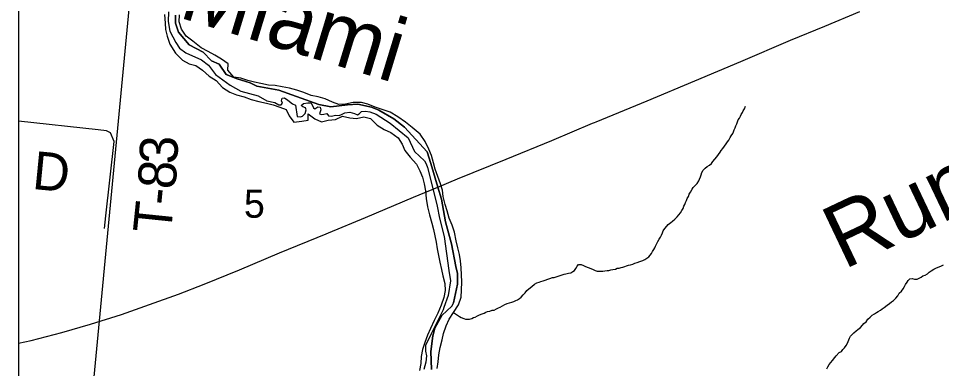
# Model space of a CAD drawing. Extents: x 0.4 to 34.4, y -2.1 to 19.9.
# Drawn here: x 3 to 4.379, y 13.669 to 14.193 of the extents above; entities that cross this region are included whole.
import ezdxf

# ---------------------------------------------------------------- set-up
doc = ezdxf.new("R2010")
doc.units = 0
for name, color, linetype in [('GM_X_County', 7, 'Continuous'), ('GM_X_Interstate_Route', 7, 'Continuous'), ('GM_X_Major_River', 7, 'Continuous'), ('GM_X_Major_River_Text', 7, 'Continuous'), ('GM_X_Minor_River', 7, 'Continuous'), ('GM_X_Minor_River_Text', 7, 'Continuous'), ('GM_X_Section', 7, 'Continuous'), ('GM_X_Section_Text', 7, 'Continuous'), ('GM_X_Township', 7, 'Continuous'), ('GM_X_Township_Road', 7, 'Continuous'), ('GM_X_Township_Road_Text', 7, 'Continuous'), ('SH_Data', 7, 'Continuous')]:
    doc.layers.add(name, color=color, linetype=linetype)

msp = doc.modelspace()

# ---------------------------------------------------------------- linework, layer by layer
at = {"layer": 'GM_X_County'}
msp.add_lwpolyline([(9.8001, 15.3423), (9.8001, 18.8357), (3.0001, 18.8357), (3.0001, 12.0357), (9.5074, 12.0357)], dxfattribs=at)
at = {"layer": 'GM_X_Interstate_Route'}
for points in [[(3.8604, 14.0372), (3.8629, 14.0382), (3.9389, 14.0693), (4.0101, 14.0992), (4.0789, 14.1281), (4.153, 14.16), (4.2044, 14.181), (4.2569, 14.2032)], [(3.4632, 13.872), (3.5184, 13.895), (3.5903, 13.9254), (3.6265, 13.9405), (3.656, 13.9528), (3.7287, 13.9823), (3.7967, 14.0104), (3.8573, 14.0359), (3.8604, 14.0372)], [(3.0001, 13.7072), (3.0189, 13.7114), (3.0649, 13.7234), (3.1078, 13.7355), (3.1538, 13.7502), (3.1959, 13.7649), (3.2393, 13.7804), (3.2777, 13.7955), (3.3301, 13.817), (3.3902, 13.8421), (3.4598, 13.8706), (3.4632, 13.872)]]:
    msp.add_lwpolyline(points, dxfattribs=at)
at = {"layer": 'GM_X_Major_River'}
for points in [[(3.2182, 14.1987), (3.2191, 14.1854), (3.2197, 14.1759), (3.2222, 14.166), (3.2262, 14.1542), (3.2348, 14.1408), (3.2452, 14.1304), (3.255, 14.1249), (3.2648, 14.1225), (3.275, 14.1155), (3.2851, 14.1066), (3.2952, 14.1), (3.3049, 14.0893), (3.3158, 14.0826), (3.326, 14.0787), (3.337, 14.0755), (3.3479, 14.0715), (3.3589, 14.0683), (3.3706, 14.0658), (3.3804, 14.0634), (3.3903, 14.0599), (3.4001, 14.0567), (3.4045, 14.0471), (3.4115, 14.0375), (3.4233, 14.0392), (3.4328, 14.0406), (3.433, 14.0501)], [(3.6269, 13.6796), (3.6278, 13.6898), (3.6299, 13.7008), (3.6327, 13.7121), (3.6351, 13.7219), (3.6387, 13.7332), (3.6434, 13.7434), (3.65, 13.7532), (3.6571, 13.7648), (3.6614, 13.7761), (3.662, 13.7867), (3.6625, 13.7989), (3.6616, 13.8095), (3.6613, 13.8201), (3.6604, 13.8304), (3.659, 13.8399), (3.6565, 13.8498), (3.6536, 13.8604), (3.6512, 13.873), (3.6479, 13.8837), (3.6435, 13.894), (3.6403, 13.905), (3.6374, 13.9145), (3.6345, 13.9267), (3.6332, 13.9362), (3.6306, 13.9457), (3.6263, 13.9564), (3.6226, 13.9675), (3.6201, 13.977), (3.6169, 13.9877), (3.6132, 13.9972), (3.6077, 14.0087), (3.5999, 14.0198), (3.5883, 14.0298), (3.5782, 14.0376), (3.5669, 14.0457), (3.5553, 14.0527), (3.5447, 14.0563), (3.533, 14.0603), (3.522, 14.0646), (3.5122, 14.0671), (3.5001, 14.0669), (3.4886, 14.0644), (3.4788, 14.0642), (3.4689, 14.0674), (3.458, 14.0725), (3.4478, 14.0753), (3.4372, 14.0777), (3.4263, 14.0821), (3.4157, 14.0853), (3.4047, 14.0885), (3.3938, 14.0905), (3.3835, 14.0922), (3.3733, 14.0927), (3.3623, 14.0952), (3.3525, 14.0976), (3.3427, 14.1), (3.3321, 14.1032), (3.3219, 14.1049), (3.3129, 14.1153), (3.3131, 14.1248), (3.3033, 14.1318), (3.2935, 14.1376), (3.2834, 14.1431), (3.2728, 14.1485), (3.2605, 14.1586), (3.2507, 14.1663), (3.2437, 14.1767), (3.24, 14.1874), (3.2406, 14.198)], [(3.433, 14.0501), (3.4427, 14.0424), (3.4525, 14.038), (3.4628, 14.0405), (3.4735, 14.0415), (3.4842, 14.0466), (3.4948, 14.0442), (3.505, 14.0429), (3.5157, 14.0458), (3.5259, 14.043), (3.536, 14.0333), (3.5461, 14.0267), (3.5563, 14.022), (3.5672, 14.0142), (3.5731, 14.0047), (3.5771, 13.9951), (3.585, 13.9851), (3.5947, 13.9751), (3.5998, 13.9648), (3.6035, 13.9553), (3.606, 13.9454), (3.6081, 13.9351), (3.6091, 13.9237), (3.6108, 13.9112), (3.614, 13.899), (3.6176, 13.8868), (3.6201, 13.8773), (3.6222, 13.8678), (3.624, 13.8582), (3.6253, 13.8484), (3.6275, 13.8381), (3.6292, 13.8282), (3.6317, 13.8175), (3.6338, 13.808), (3.6367, 13.7966), (3.6373, 13.786), (3.6356, 13.7754), (3.6316, 13.7641), (3.6265, 13.752), (3.621, 13.7411), (3.6155, 13.7291), (3.6112, 13.7193), (3.6072, 13.7083), (3.6036, 13.6978), (3.6016, 13.6872), (3.601, 13.6769), (3.599, 13.6667)], [(3.6252, 13.6694), (3.6269, 13.6796)]]:
    msp.add_lwpolyline(points, dxfattribs=at)
at = {"layer": 'GM_X_Minor_River'}
for points in [[(3.9572, 13.8629), (3.9588, 13.8659), (3.9604, 13.8689), (3.962, 13.8723), (3.9632, 13.875), (3.9652, 13.8787), (3.9683, 13.8821), (3.9703, 13.8847), (3.9742, 13.8877), (3.9769, 13.8899), (3.9804, 13.8929), (3.9839, 13.8963), (3.9866, 13.8993), (3.989, 13.9023), (3.991, 13.9057), (3.9926, 13.9087), (3.9938, 13.9121), (3.9954, 13.9147), (3.9962, 13.9177), (3.9978, 13.9208), (3.999, 13.9234), (4.0006, 13.9264), (4.0018, 13.9298), (4.0038, 13.9332), (4.0065, 13.9373), (4.0077, 13.94), (4.0113, 13.9433), (4.0136, 13.946), (4.016, 13.9497), (4.0172, 13.9524), (4.0188, 13.9561), (4.0196, 13.9588), (4.0208, 13.9626), (4.0228, 13.966), (4.0259, 13.9689), (4.0287, 13.9712), (4.0321, 13.9734), (4.0349, 13.976), (4.0372, 13.9786), (4.0403, 13.9824), (4.0431, 13.9857), (4.0458, 13.9895), (4.0482, 13.9929), (4.0498, 13.9955), (4.0521, 13.9985), (4.0545, 14.0019), (4.0569, 14.0053), (4.0592, 14.0083), (4.0612, 14.0109), (4.0632, 14.0147), (4.0644, 14.0173), (4.0668, 14.0207), (4.068, 14.0233), (4.0692, 14.026), (4.0704, 14.029), (4.0716, 14.032), (4.0728, 14.0351), (4.074, 14.0381), (4.0752, 14.0411), (4.0768, 14.0437), (4.0784, 14.0464), (4.0796, 14.049), (4.0812, 14.052), (4.0824, 14.0547), (4.0844, 14.0577), (4.086, 14.0614)], [(3.65, 13.7532), (3.6587, 13.7474), (3.6614, 13.7458), (3.6652, 13.7442), (3.6678, 13.7434), (3.6705, 13.743), (3.6735, 13.7433), (3.677, 13.7444), (3.6797, 13.7455), (3.6824, 13.7462), (3.6858, 13.748), (3.6885, 13.7495), (3.6924, 13.7513), (3.6955, 13.7524), (3.6982, 13.7535), (3.7008, 13.7546), (3.7043, 13.7553), (3.7077, 13.7564), (3.7104, 13.7567), (3.7139, 13.7585), (3.717, 13.76), (3.7197, 13.7611), (3.7231, 13.7629), (3.7266, 13.7652), (3.7301, 13.7666), (3.7336, 13.7677), (3.737, 13.7688), (3.7397, 13.7695), (3.7428, 13.7709), (3.7455, 13.772), (3.7482, 13.7739), (3.7509, 13.7761), (3.754, 13.7795), (3.7568, 13.7825), (3.7595, 13.7859), (3.7622, 13.7885), (3.7669, 13.7922), (3.7708, 13.7955), (3.7743, 13.7974), (3.7777, 13.7985), (3.7804, 13.7996), (3.7839, 13.8006), (3.7865, 13.8013), (3.7908, 13.8028), (3.7938, 13.8039), (3.7977, 13.8053), (3.8004, 13.8057), (3.803, 13.8064), (3.8061, 13.8075), (3.8092, 13.8085), (3.8119, 13.8093), (3.815, 13.8103), (3.8176, 13.8107), (3.8215, 13.8117), (3.8249, 13.8124), (3.828, 13.8143), (3.8307, 13.8161), (3.8327, 13.8188), (3.8343, 13.8222), (3.8366, 13.8248), (3.8405, 13.8251), (3.8442, 13.8235), (3.8472, 13.8219), (3.851, 13.8203), (3.8548, 13.8187), (3.8582, 13.8175), (3.8616, 13.816), (3.8642, 13.8151), (3.8696, 13.8147), (3.873, 13.815), (3.8757, 13.8153), (3.8791, 13.816), (3.8818, 13.816), (3.8849, 13.8167), (3.8876, 13.8174), (3.8918, 13.8181), (3.8945, 13.8192), (3.8971, 13.8195), (3.9002, 13.8202), (3.9029, 13.8209), (3.9056, 13.822), (3.9083, 13.8227), (3.911, 13.8238), (3.9144, 13.8245), (3.9175, 13.8256), (3.9206, 13.8267), (3.924, 13.8277), (3.9279, 13.8292), (3.9325, 13.831), (3.9356, 13.8325), (3.9386, 13.8343), (3.9414, 13.8362), (3.9433, 13.8388), (3.9453, 13.8414), (3.9469, 13.8441), (3.9488, 13.8471), (3.9504, 13.8497), (3.9516, 13.8524), (3.9536, 13.8561), (3.9552, 13.8595), (3.9572, 13.8629)], [(4.2401, 13.7124), (4.241, 13.715), (4.2429, 13.7177), (4.2476, 13.7229), (4.2511, 13.7255), (4.2538, 13.7277), (4.2577, 13.7307), (4.2605, 13.7341), (4.2628, 13.7367), (4.2659, 13.7393), (4.2687, 13.7431), (4.2722, 13.7464), (4.2753, 13.7494), (4.2784, 13.7513), (4.2815, 13.7531), (4.2842, 13.7546), (4.2873, 13.7564), (4.29, 13.7587), (4.2931, 13.7605), (4.2974, 13.7639), (4.3008, 13.7665), (4.304, 13.7691), (4.3071, 13.7713), (4.3106, 13.7746), (4.3133, 13.778), (4.3153, 13.7818), (4.3188, 13.7848), (4.3212, 13.7885), (4.3235, 13.7919), (4.3251, 13.7949), (4.3275, 13.7983), (4.3291, 13.8009), (4.3314, 13.8036), (4.3349, 13.8039), (4.3383, 13.8031), (4.3421, 13.803), (4.3452, 13.8045), (4.3482, 13.8059), (4.351, 13.8078), (4.3544, 13.8092), (4.3575, 13.8111), (4.3602, 13.8133), (4.3633, 13.8152), (4.3672, 13.8177), (4.3703, 13.8192), (4.3737, 13.8207), (4.3776, 13.8225), (4.3814, 13.8243)], [(4.2075, 13.6689), (4.2091, 13.6719), (4.2111, 13.6753), (4.2135, 13.6786), (4.2158, 13.6816), (4.2193, 13.6858), (4.2213, 13.6884), (4.226, 13.6933), (4.2291, 13.6951), (4.2314, 13.6977), (4.2338, 13.7003), (4.2365, 13.7037), (4.2385, 13.7071), (4.2393, 13.7097), (4.2401, 13.7124)]]:
    msp.add_lwpolyline(points, dxfattribs=at)
at = {"layer": 'GM_X_Section'}
msp.add_line((3.0001, 14.5041), (3.0001, 13.5939), dxfattribs=at)
for points in [[(3.0001, 13.5939), (3.106, 13.5839), (3.192, 14.4845), (3.0001, 14.5041)], [(3.106, 13.5839), (3.192, 14.4845)], [(3.2242, 14.2025), (3.2236, 14.1882), (3.2264, 14.1737), (3.2352, 14.1569), (3.2407, 14.1481), (3.2501, 14.1415), (3.2737, 14.1309), (3.2838, 14.1227), (3.2942, 14.1089), (3.3163, 14.093), (3.332, 14.084), (3.358, 14.0771), (3.3711, 14.0697), (3.3832, 14.0669), (3.3888, 14.0637), (3.3926, 14.0637), (3.3946, 14.0659), (3.3931, 14.0697), (3.3939, 14.0735), (3.3973, 14.0738), (3.4022, 14.0707), (3.4093, 14.0649), (3.4138, 14.0629), (3.4166, 14.0462), (3.4215, 14.0454), (3.4245, 14.0465), (3.4284, 14.0506), (3.43, 14.0562), (3.4289, 14.0589), (3.4248, 14.0605), (3.4221, 14.0624), (3.4259, 14.0655), (3.4321, 14.0664), (3.4374, 14.0663), (3.4406, 14.059), (3.4429, 14.0575), (3.4471, 14.0605), (3.4505, 14.06), (3.4516, 14.0562), (3.4499, 14.0502), (3.4522, 14.049), (3.456, 14.0497), (3.4609, 14.0507), (3.4632, 14.0473), (3.4677, 14.0468), (3.4734, 14.0479), (3.4791, 14.0474), (3.4825, 14.0489), (3.4875, 14.0518), (3.4951, 14.0528), (3.5018, 14.0508), (3.5067, 14.0488), (3.509, 14.0499), (3.5125, 14.0536), (3.5182, 14.0543), (3.525, 14.053), (3.5344, 14.0495), (3.555, 14.0362), (3.5819, 14.0142), (3.5914, 13.994), (3.6065, 13.9797), (3.609, 13.9753), (3.611, 13.9701), (3.617, 13.9466), (3.6255, 13.9119), (3.629, 13.8941), (3.6357, 13.8667), (3.6428, 13.8158), (3.6452, 13.8003), (3.6421, 13.7784), (3.6354, 13.7604), (3.6342, 13.7573), (3.6165, 13.7212), (3.6079, 13.7036), (3.6082, 13.6956), (3.6095, 13.6884), (3.6086, 13.679), (3.6054, 13.668)]]:
    msp.add_lwpolyline(points, dxfattribs=at)
at = {"layer": 'GM_X_Township'}
msp.add_line((3.0001, 17.934), (3.0001, 12.5191), dxfattribs=at)
for points in [[(3.617, 13.6682), (3.616, 13.6948), (3.6189, 13.7184), (3.6219, 13.7298), (3.6325, 13.7485), (3.6475, 13.7628), (3.6498, 13.7675), (3.6556, 13.7953), (3.6556, 13.8113), (3.6533, 13.822), (3.6467, 13.8559), (3.6377, 13.8885), (3.632, 13.9223), (3.6265, 13.9405), (3.6158, 13.9757), (3.6104, 13.9933), (3.5769, 14.0301), (3.5606, 14.0426), (3.5384, 14.0556), (3.5274, 14.0602), (3.5072, 14.0644), (3.4917, 14.0634), (3.4666, 14.0606), (3.4486, 14.0638), (3.389, 14.0856), (3.3562, 14.0913), (3.3464, 14.0966), (3.3266, 14.1022), (3.3101, 14.109), (3.3, 14.1241), (3.2886, 14.1295), (3.2761, 14.1425), (3.2553, 14.1531), (3.2392, 14.1724), (3.2349, 14.1856), (3.2347, 14.1976)], [(3.2347, 14.1976), (3.2349, 14.1856), (3.2392, 14.1724), (3.2553, 14.1531), (3.2761, 14.1425), (3.2886, 14.1295), (3.3, 14.1241), (3.3101, 14.109), (3.3266, 14.1022), (3.3464, 14.0966), (3.3562, 14.0913), (3.389, 14.0856), (3.4486, 14.0638), (3.4666, 14.0606), (3.4917, 14.0634), (3.5072, 14.0644), (3.5274, 14.0602), (3.5384, 14.0556), (3.5606, 14.0426), (3.5769, 14.0301), (3.6104, 13.9933), (3.6158, 13.9757), (3.6265, 13.9405), (3.632, 13.9223), (3.6377, 13.8885), (3.6467, 13.8559), (3.6533, 13.822), (3.6556, 13.8113), (3.6556, 13.7953), (3.6498, 13.7675), (3.6475, 13.7628), (3.6325, 13.7485), (3.6219, 13.7298), (3.6189, 13.7184), (3.616, 13.6948), (3.617, 13.6682)]]:
    msp.add_lwpolyline(points, dxfattribs=at)
at = {"layer": 'GM_X_Township_Road'}
msp.add_lwpolyline([(3.1285, 13.8787), (3.1308, 13.8978), (3.143, 14.0087), (3.1375, 14.0217), (3.1318, 14.0248), (3.1193, 14.0261), (3.0001, 14.0392)], dxfattribs=at)
at = {"layer": 'SH_Data'}
msp.add_line((3.0001, 18.8357), (3.0001, 12.0357), dxfattribs=at)

# ---------------------------------------------------------------- texts
at = {"layer": 'GM_X_Major_River_Text'}
msp.add_text('Miami', height=0.09469, rotation=343.0376, dxfattribs=at).set_placement((3.2371, 14.1949))
at = {"layer": 'GM_X_Minor_River_Text'}
msp.add_text('Run', height=0.0947, rotation=25.4036, dxfattribs=at).set_placement((4.2326, 13.8167))
at = {"layer": 'GM_X_Section_Text'}
msp.add_text('5', height=0.0419, rotation=0, dxfattribs=at).set_placement((3.3369, 13.8948))
at = {"layer": 'GM_X_Township_Road_Text'}
for s, rotation, p in [('3', 88.2652, (3.2374, 13.9743)), ('D', 354.4544, (3.0195, 13.938)), ('8', 85.1481, (3.2342, 13.9361)), ('-', 84.3308, (3.2319, 13.912)), ('T', 84.1269, (3.2275, 13.8695))]:
    msp.add_text(s, height=0.0568, rotation=rotation, dxfattribs=at).set_placement(p)

doc.saveas('drawing.dxf')
